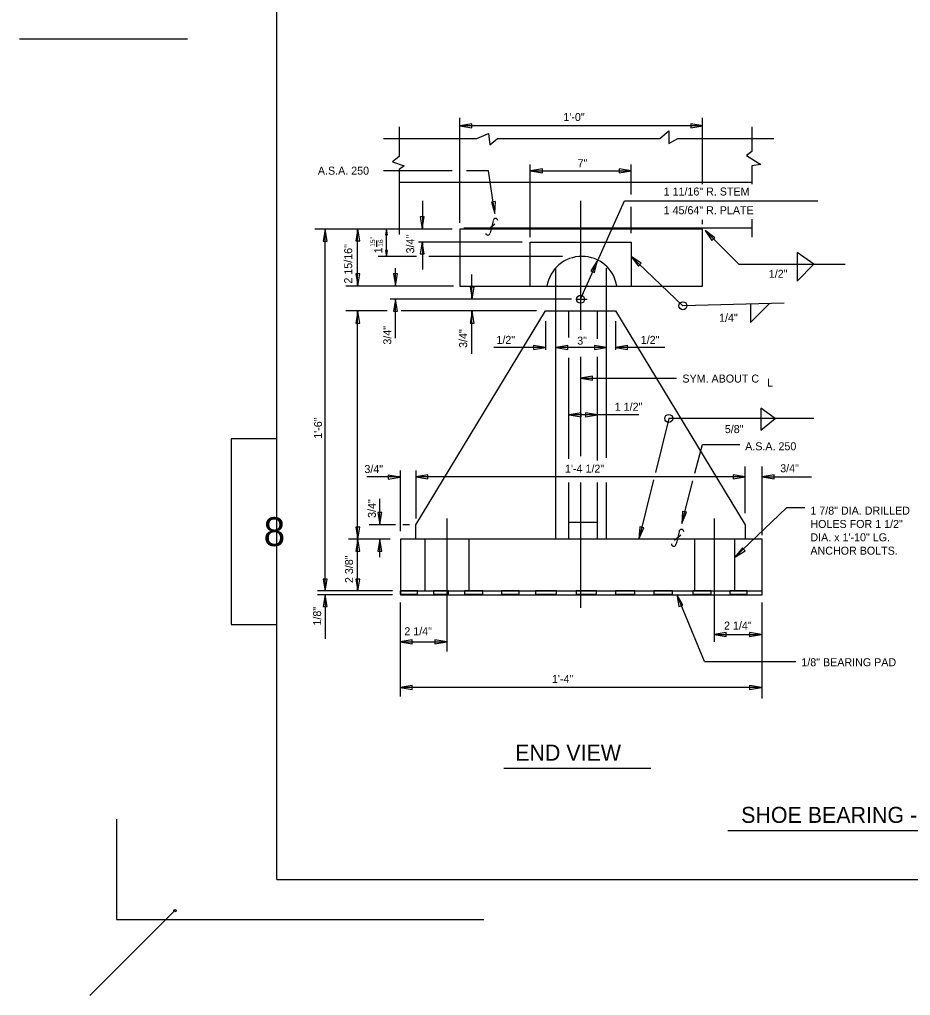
# Model space of a CAD drawing. Extents: x -1.11 to 1.95, y -0.95 to 1.09.
# Drawn here: x -1.111 to -0.183, y -0.94 to 0.076 of the extents above; entities that cross this region are included whole.
import ezdxf

# ---------------------------------------------------------------- set-up
doc = ezdxf.new("R2010")
doc.units = 0
for name, color, linetype in [('Level 1', 7, 'Continuous'), ('Level 2', 7, 'Continuous'), ('Level 3', 7, 'Continuous'), ('Level 37', 7, 'Continuous'), ('Level 49', 7, 'Continuous')]:
    doc.layers.add(name, color=color, linetype=linetype)

msp = doc.modelspace()

# ---------------------------------------------------------------- linework, layer by layer
at = {"layer": 'Level 1'}
for p, q in [((-0.8431, -0.8191), (-0.8431, 0.9309)), ((-0.6523, -0.1353), (-0.6523, -0.026)), ((-0.3998, -0.0951), (-0.3998, -0.026)), ((-0.7157, -0.0355), (-0.7157, -0.0665)), ((-0.6399, -0.0323), (-0.6524, -0.0343)), ((-0.6524, -0.0343), (-0.6399, -0.0364)), ((-0.6523, -0.0342), (-0.4012, -0.0342)), ((-0.6399, -0.0364), (-0.6399, -0.0323)), ((-0.4443, -0.0476), (-0.4349, -0.0395)), ((-0.4349, -0.0395), (-0.4349, -0.053)), ((-0.4119, -0.0323), (-0.4119, -0.0364)), ((-0.3994, -0.0343), (-0.4119, -0.0323)), ((-0.4119, -0.0364), (-0.3994, -0.0343)), ((-0.3485, -0.0355), (-0.3485, -0.0611)), ((-0.7318, -0.0476), (-0.6347, -0.0476)), ((-0.6347, -0.0476), (-0.6225, -0.0423)), ((-0.6225, -0.0423), (-0.6212, -0.0543)), ((-0.6212, -0.0543), (-0.6131, -0.0476)), ((-0.6131, -0.0476), (-0.4443, -0.0476)), ((-0.4349, -0.053), (-0.4254, -0.0476)), ((-0.4254, -0.0476), (-0.3256, -0.0476)), ((-0.7157, -0.0665), (-0.7224, -0.0719)), ((-0.3485, -0.0611), (-0.3539, -0.0652)), ((-0.3539, -0.0652), (-0.3391, -0.0746)), ((-0.7224, -0.0719), (-0.7103, -0.076)), ((-0.7103, -0.076), (-0.7157, -0.08)), ((-0.7157, -0.08), (-0.7157, -0.1475)), ((-0.5793, -0.1503), (-0.5793, -0.0746)), ((-0.5663, -0.0793), (-0.5788, -0.0814)), ((-0.5663, -0.0835), (-0.5663, -0.0793)), ((-0.4865, -0.0793), (-0.4865, -0.0835)), ((-0.474, -0.0814), (-0.4865, -0.0793)), ((-0.474, -0.1061), (-0.474, -0.0746)), ((-0.3391, -0.0746), (-0.3485, -0.076)), ((-0.3485, -0.076), (-0.3485, -0.0951)), ((-0.6603, -0.0813), (-0.7318, -0.0813)), ((-0.6225, -0.0813), (-0.6455, -0.0813)), ((-0.6158, -0.1259), (-0.6225, -0.0813)), ((-0.5793, -0.0813), (-0.474, -0.0813)), ((-0.5788, -0.0814), (-0.5663, -0.0835)), ((-0.4865, -0.0835), (-0.474, -0.0814)), ((-0.6913, -0.1124), (-0.6913, -0.1421)), ((-0.6153, -0.1133), (-0.6195, -0.1138)), ((-0.6195, -0.1138), (-0.6158, -0.1259)), ((-0.6158, -0.1259), (-0.6153, -0.1133)), ((-0.5267, -0.215), (-0.4808, -0.1124)), ((-0.4808, -0.1124), (-0.2797, -0.1124)), ((-0.474, -0.1462), (-0.474, -0.1188)), ((-0.6936, -0.1293), (-0.6915, -0.1418)), ((-0.6894, -0.1293), (-0.6936, -0.1293)), ((-0.6915, -0.1418), (-0.6894, -0.1293)), ((-0.3485, -0.1316), (-0.3485, -0.1503)), ((-0.6603, -0.1421), (-0.8034, -0.1421)), ((-0.7926, -0.1422), (-0.7947, -0.1547)), ((-0.7926, -0.5188), (-0.7926, -0.1421)), ((-0.7905, -0.1547), (-0.7926, -0.1422)), ((-0.7585, -0.1418), (-0.7606, -0.1543)), ((-0.7588, -0.2015), (-0.7588, -0.1421)), ((-0.7564, -0.1543), (-0.7585, -0.1418)), ((-0.7288, -0.1418), (-0.7298, -0.148)), ((-0.7292, -0.1421), (-0.7292, -0.1705)), ((-0.7278, -0.148), (-0.7288, -0.1418)), ((-0.3998, -0.1421), (-0.6523, -0.1421)), ((-0.6523, -0.1421), (-0.6523, -0.2015)), ((-0.6159, -0.1368), (-0.6225, -0.1425)), ((-0.6177, -0.1332), (-0.6208, -0.146)), ((-0.3998, -0.1368), (-0.3998, -0.1324)), ((-0.3998, -0.2015), (-0.3998, -0.1421)), ((-0.7298, -0.148), (-0.7278, -0.148)), ((-0.3971, -0.1435), (-0.362, -0.1786)), ((-0.387, -0.1512), (-0.3971, -0.1435)), ((-0.3971, -0.1435), (-0.3901, -0.154)), ((-0.3901, -0.154), (-0.387, -0.1512)), ((-0.7947, -0.1547), (-0.7905, -0.1547)), ((-0.7606, -0.1543), (-0.7564, -0.1543)), ((-0.739, -0.1604), (-0.739, -0.1537)), ((-0.5874, -0.1556), (-0.6954, -0.1556)), ((-0.6915, -0.1553), (-0.6936, -0.1678)), ((-0.6894, -0.1678), (-0.6915, -0.1553)), ((-0.6913, -0.1556), (-0.6913, -0.184)), ((-0.5793, -0.2015), (-0.5793, -0.1556)), ((-0.5793, -0.1556), (-0.474, -0.1556)), ((-0.474, -0.1556), (-0.474, -0.2015)), ((-0.6974, -0.1705), (-0.7373, -0.1705)), ((-0.7298, -0.1644), (-0.7288, -0.1707)), ((-0.7278, -0.1644), (-0.7298, -0.1644)), ((-0.7288, -0.1707), (-0.7278, -0.1644)), ((-0.6936, -0.1678), (-0.6894, -0.1678)), ((-0.5456, -0.1705), (-0.6847, -0.1705)), ((-0.4201, -0.2218), (-0.474, -0.1705)), ((-0.4635, -0.1775), (-0.474, -0.1705)), ((-0.474, -0.1705), (-0.4664, -0.1806)), ((-0.3013, -0.1664), (-0.3013, -0.1961)), ((-0.2838, -0.1786), (-0.3013, -0.1664)), ((-0.7198, -0.1826), (-0.7198, -0.2015)), ((-0.5089, -0.1748), (-0.5159, -0.1854)), ((-0.5122, -0.1872), (-0.5089, -0.1748)), ((-0.4664, -0.1806), (-0.4635, -0.1775)), ((-0.362, -0.1786), (-0.2513, -0.1786)), ((-0.3013, -0.1961), (-0.2838, -0.1786)), ((-0.7606, -0.1887), (-0.7585, -0.2012)), ((-0.7564, -0.1887), (-0.7606, -0.1887)), ((-0.7585, -0.2012), (-0.7564, -0.1887)), ((-0.7216, -0.1887), (-0.7195, -0.2012)), ((-0.7174, -0.1887), (-0.7216, -0.1887)), ((-0.7195, -0.2012), (-0.7174, -0.1887)), ((-0.6401, -0.1893), (-0.6401, -0.215)), ((-0.5159, -0.1854), (-0.5122, -0.1872)), ((-0.659, -0.2015), (-0.771, -0.2015)), ((-0.6523, -0.2015), (-0.3998, -0.2015)), ((-0.6418, -0.2023), (-0.6397, -0.2148)), ((-0.6376, -0.2023), (-0.6418, -0.2023)), ((-0.6397, -0.2148), (-0.6376, -0.2023)), ((-0.5523, -0.2272), (-0.5523, -0.2015)), ((-0.4997, -0.2272), (-0.4997, -0.2015)), ((-0.5362, -0.215), (-0.7251, -0.215)), ((-0.7195, -0.2148), (-0.7216, -0.2273)), ((-0.7198, -0.215), (-0.7198, -0.2555)), ((-0.7174, -0.2273), (-0.7195, -0.2148)), ((-0.5308, -0.215), (-0.5199, -0.215)), ((-0.3148, -0.2191), (-0.4201, -0.2218)), ((-0.3498, -0.2393), (-0.3296, -0.2191)), ((-0.3498, -0.2204), (-0.3498, -0.2393)), ((-0.728, -0.2272), (-0.771, -0.2272)), ((-0.7585, -0.2275), (-0.7606, -0.24)), ((-0.7588, -0.5188), (-0.7588, -0.2272)), ((-0.7564, -0.24), (-0.7585, -0.2275)), ((-0.7216, -0.2273), (-0.7174, -0.2273)), ((-0.5726, -0.2272), (-0.7135, -0.2272)), ((-0.6981, -0.4499), (-0.5632, -0.2272)), ((-0.6397, -0.2275), (-0.6418, -0.24)), ((-0.6401, -0.2272), (-0.6401, -0.2717)), ((-0.6376, -0.24), (-0.6397, -0.2275)), ((-0.5632, -0.2272), (-0.4903, -0.2272)), ((-0.5388, -0.2547), (-0.5388, -0.2272)), ((-0.5092, -0.2563), (-0.5092, -0.2272)), ((-0.4903, -0.2272), (-0.3553, -0.4499)), ((-0.7606, -0.24), (-0.7564, -0.24)), ((-0.6418, -0.24), (-0.6376, -0.24)), ((-0.5632, -0.2379), (-0.5632, -0.2677)), ((-0.4903, -0.2379), (-0.4903, -0.2677)), ((-0.5758, -0.2632), (-0.5758, -0.2673)), ((-0.5633, -0.2653), (-0.5758, -0.2632)), ((-0.5398, -0.2632), (-0.5523, -0.2653)), ((-0.5398, -0.2673), (-0.5398, -0.2632)), ((-0.5121, -0.2632), (-0.5121, -0.2673)), ((-0.4996, -0.2653), (-0.5121, -0.2632)), ((-0.4778, -0.2632), (-0.4903, -0.2653)), ((-0.4778, -0.2673), (-0.4778, -0.2632)), ((-0.6171, -0.2649), (-0.5632, -0.2649)), ((-0.5758, -0.2673), (-0.5633, -0.2653)), ((-0.5523, -0.2649), (-0.4997, -0.2649)), ((-0.5523, -0.2653), (-0.5398, -0.2673)), ((-0.5121, -0.2673), (-0.4996, -0.2653)), ((-0.4903, -0.2649), (-0.4389, -0.2649)), ((-0.4903, -0.2653), (-0.4778, -0.2673)), ((-0.5388, -0.3812), (-0.5388, -0.2759)), ((-0.5092, -0.3828), (-0.5092, -0.2751)), ((-0.5143, -0.295), (-0.5268, -0.2971)), ((-0.5268, -0.2971), (-0.5143, -0.2992)), ((-0.5267, -0.2973), (-0.4268, -0.2973)), ((-0.5143, -0.2992), (-0.5143, -0.295)), ((-0.5388, -0.3352), (-0.4659, -0.3352)), ((-0.5262, -0.3333), (-0.5387, -0.3353)), ((-0.5387, -0.3353), (-0.5262, -0.3374)), ((-0.5262, -0.3374), (-0.5262, -0.3333)), ((-0.5214, -0.3333), (-0.5214, -0.3374)), ((-0.5089, -0.3353), (-0.5214, -0.3333)), ((-0.5214, -0.3374), (-0.5089, -0.3353)), ((-0.3391, -0.3284), (-0.3391, -0.3513)), ((-0.3242, -0.3392), (-0.3391, -0.3284)), ((-0.4349, -0.3392), (-0.4488, -0.3953)), ((-0.2838, -0.3392), (-0.4349, -0.3392)), ((-0.3391, -0.3513), (-0.3242, -0.3392)), ((-0.4077, -0.3963), (-0.3998, -0.3662)), ((-0.3998, -0.3662), (-0.3607, -0.3662)), ((-0.7143, -0.4567), (-0.7143, -0.3932)), ((-0.6981, -0.3932), (-0.6981, -0.4432)), ((-0.3553, -0.4378), (-0.3553, -0.3892)), ((-0.3377, -0.4607), (-0.3377, -0.3892)), ((-0.7143, -0.3999), (-0.7494, -0.3999)), ((-0.7269, -0.3982), (-0.7269, -0.4023)), ((-0.7144, -0.4003), (-0.7269, -0.3982)), ((-0.7269, -0.4023), (-0.7144, -0.4003)), ((-0.6858, -0.3978), (-0.6983, -0.3998)), ((-0.6983, -0.3998), (-0.6858, -0.4019)), ((-0.3553, -0.3999), (-0.6981, -0.3999)), ((-0.6858, -0.4019), (-0.6858, -0.3978)), ((-0.5388, -0.4648), (-0.5388, -0.4058)), ((-0.5092, -0.4648), (-0.5092, -0.4058)), ((-0.4508, -0.4032), (-0.4659, -0.4648)), ((-0.4214, -0.4485), (-0.4098, -0.4041)), ((-0.3678, -0.3978), (-0.3678, -0.4019)), ((-0.3553, -0.3998), (-0.3678, -0.3978)), ((-0.3678, -0.4019), (-0.3553, -0.3998)), ((-0.3377, -0.3999), (-0.2864, -0.3999)), ((-0.325, -0.3978), (-0.3375, -0.3998)), ((-0.3375, -0.3998), (-0.325, -0.4019)), ((-0.325, -0.4019), (-0.325, -0.3978)), ((-0.7359, -0.4229), (-0.7359, -0.4499)), ((-0.7377, -0.437), (-0.7356, -0.4495)), ((-0.7335, -0.437), (-0.7377, -0.437)), ((-0.7356, -0.4495), (-0.7335, -0.437)), ((-0.4204, -0.4359), (-0.4214, -0.4485)), ((-0.4214, -0.4485), (-0.4163, -0.4369)), ((-0.4163, -0.4369), (-0.4204, -0.4359)), ((-0.3121, -0.4323), (-0.3661, -0.4837)), ((-0.2932, -0.4323), (-0.3121, -0.4323)), ((-0.5388, -0.4472), (-0.5092, -0.4472)), ((-0.7606, -0.4523), (-0.7585, -0.4648)), ((-0.7564, -0.4523), (-0.7606, -0.4523)), ((-0.7585, -0.4648), (-0.7564, -0.4523)), ((-0.7195, -0.4499), (-0.7467, -0.4499)), ((-0.7048, -0.4499), (-0.7118, -0.4499)), ((-0.6981, -0.4648), (-0.6981, -0.4499)), ((-0.4649, -0.4521), (-0.4659, -0.4648)), ((-0.4659, -0.4648), (-0.4609, -0.4531)), ((-0.4609, -0.4531), (-0.4649, -0.4521)), ((-0.4241, -0.4571), (-0.4272, -0.4698)), ((-0.3553, -0.4499), (-0.3553, -0.4648)), ((-0.7251, -0.4648), (-0.7683, -0.4648)), ((-0.7585, -0.4648), (-0.7606, -0.4773)), ((-0.7564, -0.4773), (-0.7585, -0.4648)), ((-0.7356, -0.4648), (-0.7377, -0.4773)), ((-0.7359, -0.4648), (-0.7359, -0.4837)), ((-0.7335, -0.4773), (-0.7356, -0.4648)), ((-0.3377, -0.4648), (-0.7143, -0.4648)), ((-0.7143, -0.4648), (-0.7143, -0.5228)), ((-0.4223, -0.4606), (-0.429, -0.4663)), ((-0.3377, -0.5228), (-0.3377, -0.4648)), ((-0.7606, -0.4773), (-0.7564, -0.4773)), ((-0.7377, -0.4773), (-0.7335, -0.4773)), ((-0.358, -0.4738), (-0.3661, -0.4837)), ((-0.3661, -0.4837), (-0.3553, -0.477)), ((-0.3553, -0.477), (-0.358, -0.4738)), ((-0.7946, -0.5066), (-0.7925, -0.5191)), ((-0.7904, -0.5066), (-0.7946, -0.5066)), ((-0.7925, -0.5191), (-0.7904, -0.5066)), ((-0.7606, -0.5066), (-0.7585, -0.5191)), ((-0.7564, -0.5066), (-0.7606, -0.5066)), ((-0.7585, -0.5191), (-0.7564, -0.5066)), ((-0.7224, -0.5188), (-0.8007, -0.5188)), ((-0.7224, -0.5228), (-0.8007, -0.5228)), ((-0.7925, -0.5225), (-0.7946, -0.535)), ((-0.7926, -0.5228), (-0.7926, -0.5687)), ((-0.7904, -0.535), (-0.7925, -0.5225)), ((-0.7143, -0.5188), (-0.3377, -0.5188)), ((-0.7143, -0.5228), (-0.3377, -0.5228)), ((-0.3978, -0.5921), (-0.4266, -0.5225)), ((-0.4203, -0.5335), (-0.4266, -0.5225)), ((-0.4266, -0.5225), (-0.4243, -0.5349)), ((-0.7946, -0.535), (-0.7904, -0.535)), ((-0.7144, -0.5308), (-0.7144, -0.6288)), ((-0.4243, -0.5349), (-0.4203, -0.5335)), ((-0.3379, -0.5308), (-0.3379, -0.6308)), ((-0.3751, -0.562), (-0.3876, -0.5641)), ((-0.3876, -0.5641), (-0.3383, -0.5641)), ((-0.3876, -0.5641), (-0.3751, -0.5662)), ((-0.3751, -0.5662), (-0.3751, -0.562)), ((-0.3508, -0.562), (-0.3508, -0.5662)), ((-0.3383, -0.5641), (-0.3508, -0.562)), ((-0.3508, -0.5662), (-0.3383, -0.5641)), ((-0.7019, -0.5697), (-0.7144, -0.5718)), ((-0.7144, -0.5718), (-0.7019, -0.5738)), ((-0.7144, -0.5718), (-0.666, -0.5718)), ((-0.7019, -0.5738), (-0.7019, -0.5697)), ((-0.6785, -0.5697), (-0.6785, -0.5738)), ((-0.666, -0.5718), (-0.6785, -0.5697)), ((-0.6785, -0.5738), (-0.666, -0.5718)), ((-0.3978, -0.5921), (-0.3027, -0.5921)), ((-0.7019, -0.6172), (-0.7144, -0.6193)), ((-0.7144, -0.6191), (-0.3379, -0.6191)), ((-0.7144, -0.6193), (-0.7019, -0.6213)), ((-0.7019, -0.6213), (-0.7019, -0.6172)), ((-0.3508, -0.6172), (-0.3508, -0.6213)), ((-0.3383, -0.6193), (-0.3508, -0.6172)), ((-0.3508, -0.6213), (-0.3383, -0.6193)), ((-0.6066, -0.7033), (-0.4537, -0.7033)), ((-1.0098, -0.7564), (-1.0098, -0.8608)), ((-0.3733, -0.7681), (-0.0737, -0.7681)), ((-0.8431, -0.8191), (1.7715, -0.8191)), ((-1.0098, -0.8608), (-0.6274, -0.8608))]:
    msp.add_line(p, q, dxfattribs=at)
for points in [[(-0.8431, -0.3604), (-0.8904, -0.3604), (-0.8904, -0.5538), (-0.8431, -0.5538)], [(-0.7146, -0.5186), (-0.7146, -0.5223), (-0.6965, -0.5223), (-0.6965, -0.5186)], [(-0.6799, -0.5186), (-0.6799, -0.5223), (-0.6641, -0.5223), (-0.6641, -0.5186)], [(-0.6474, -0.5186), (-0.6474, -0.5223), (-0.6286, -0.5223), (-0.6286, -0.5186)], [(-0.6089, -0.5186), (-0.6089, -0.5223), (-0.5908, -0.5223), (-0.5908, -0.5186)], [(-0.5735, -0.5186), (-0.5735, -0.5223), (-0.5516, -0.5223), (-0.5516, -0.5186)], [(-0.5313, -0.5186), (-0.5313, -0.5223), (-0.5101, -0.5223), (-0.5101, -0.5186)], [(-0.4904, -0.5186), (-0.4904, -0.5223), (-0.4701, -0.5223), (-0.4701, -0.5186)], [(-0.4504, -0.5186), (-0.4504, -0.5223), (-0.4308, -0.5223), (-0.4308, -0.5186)], [(-0.4097, -0.5186), (-0.4097, -0.5223), (-0.3908, -0.5223), (-0.3908, -0.5186)], [(-0.3713, -0.5186), (-0.3713, -0.5223), (-0.3531, -0.5223), (-0.3531, -0.5186)]]:
    msp.add_lwpolyline(points, close=True, dxfattribs=at)
for centre in [(-0.5267, -0.215), (-0.4201, -0.2218), (-0.4349, -0.3392)]:
    msp.add_circle(centre, 0.00417, dxfattribs=at)
for centre, radius, start, end in [((-0.6153, -0.1333), 0.00242, 3.9452, 176.0548), ((-0.6232, -0.1458), 0.00243, 185.9061, 354.0939), ((-0.4217, -0.4572), 0.00242, 1.9749, 178.0251), ((-0.4296, -0.4697), 0.00251, 183.8141, 356.0548)]:
    msp.add_arc(centre, radius, start, end, dxfattribs=at)
at = {"layer": 'Level 2'}
for p, q in [((-0.3485, -0.0935), (-0.7157, -0.0935)), ((-0.6482, -0.1408), (-0.3485, -0.1408)), ((-0.5523, -0.2015), (-0.5523, -0.1826)), ((-0.4997, -0.2015), (-0.4997, -0.1826)), ((-0.5523, -0.4648), (-0.5523, -0.2272)), ((-0.4997, -0.3803), (-0.4997, -0.2272)), ((-0.4997, -0.4648), (-0.4997, -0.4058)), ((-0.6887, -0.4648), (-0.6887, -0.5188)), ((-0.6428, -0.5188), (-0.6428, -0.4648)), ((-0.4079, -0.4648), (-0.4079, -0.5188)), ((-0.3661, -0.5188), (-0.3661, -0.4648)), ((-1.0375, -0.94), (-0.9491, -0.8517))]:
    msp.add_line(p, q, dxfattribs=at)
msp.add_arc((-0.5253, -0.2073), 0.0369, 9.1005, 170.8995, dxfattribs=at)
at = {"layer": 'Level 3'}
for p, q in [((-0.5267, -0.1124), (-0.5267, -0.247)), ((-0.5267, -0.2751), (-0.5267, -0.3786)), ((-0.5267, -0.4058), (-0.5267, -0.5363)), ((-0.6658, -0.4432), (-0.6658, -0.5538)), ((-0.3877, -0.4432), (-0.3877, -0.5538)), ((-0.666, -0.5531), (-0.666, -0.5819)), ((-0.3876, -0.5531), (-0.3876, -0.5718))]:
    msp.add_line(p, q, dxfattribs=at)
at = {"layer": 'Level 37'}
msp.add_line((-0.936, 0.0559), (-1.1109, 0.0559), dxfattribs=at)
at = {"layer": 'Level 49'}
msp.add_circle((-0.9491, -0.8517), 0.00127, dxfattribs=at)

# ---------------------------------------------------------------- texts
at = {"layer": 'Level 1'}
for s, height, p in [('1\'-0"', 0.00833, (-0.5446, -0.0294)), ('7"', 0.00833, (-0.5298, -0.0775)), ('A.S.A. 250', 0.00833, (-0.8002, -0.0853)), ('1 11/16" R. STEM', 0.008334, (-0.4402, -0.107)), ('1 45/64" R. PLATE', 0.008334, (-0.4402, -0.1265)), ('1/2"', 0.00833, (-0.3307, -0.1927)), ('1/4"', 0.00833, (-0.3825, -0.2385)), ('1/2"', 0.00833, (-0.6143, -0.2615)), ('3"', 0.00833, (-0.5302, -0.2623)), ('1/2"', 0.00833, (-0.464, -0.2615)), ('SYM. ABOUT C', 0.008334, (-0.4207, -0.3018)), ('L', 0.00833, (-0.3324, -0.306)), ('1 1/2"', 0.00833, (-0.4911, -0.3311)), ('5/8"', 0.00833, (-0.3765, -0.3544)), ('A.S.A. 250', 0.00833, (-0.3553, -0.3723)), ('3/4"', 0.00833, (-0.7518, -0.396)), ('1\'-4 1/2"', 0.00833, (-0.5429, -0.3956)), ('3/4"', 0.00833, (-0.3188, -0.3952)), ('1 7/8" DIA. DRILLED', 0.008334, (-0.2874, -0.4393)), ('8', 0.0301, (-0.8567, -0.4721)), ('HOLES FOR 1 1/2"', 0.008334, (-0.2874, -0.4532)), ('DIA. x 1\'-10" LG.', 0.008334, (-0.2874, -0.4671)), ('ANCHOR BOLTS.', 0.008334, (-0.2874, -0.481)), ('2 1/4"', 0.00833, (-0.7102, -0.5649)), ('2 1/4"', 0.00833, (-0.3773, -0.559)), ('1/8" BEARING PAD', 0.008334, (-0.2968, -0.5972)), ('1\'-4"', 0.00833, (-0.5565, -0.6146)), ('END VIEW', 0.01667, (-0.5948, -0.6955)), ('SHOE BEARING - FIXED', 0.016667, (-0.3595, -0.7603))]:
    msp.add_text(s, height=height, dxfattribs=at).set_placement(p)
for s, height, p in [('15"', 0.005, (-0.7407, -0.1604)), ('3/4"', 0.00833, (-0.6999, -0.1673)), ('2 15/16"', 0.00833, (-0.7645, -0.1987)), ('1', 0.00833, (-0.7331, -0.1673)), ('16', 0.005, (-0.7323, -0.1604)), ('3/4"', 0.00833, (-0.7238, -0.2623)), ('3/4"', 0.00833, (-0.6448, -0.2657)), ('1\'-6"', 0.00833, (-0.7959, -0.3603)), ('3/4"', 0.00833, (-0.7398, -0.4427)), ('2 3/8"', 0.00833, (-0.7636, -0.5106)), ('1/8"', 0.00833, (-0.7968, -0.5548))]:
    msp.add_text(s, height=height, rotation=90, dxfattribs=at).set_placement(p)

doc.saveas('drawing.dxf')
